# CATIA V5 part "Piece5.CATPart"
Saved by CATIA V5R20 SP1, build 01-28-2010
Part number: Piece5
Bounding box of the stored display mesh (mm): x -22.654 to 20.303, y 48.687 to 194.568, z -19.994 to 19.994
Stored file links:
  C:\Users\RENARD Simon\Documents\Cours IFMA\2ème année\IAO\Piece5.CATPart
  C:\Users\RENARD Simon\Documents\Cours IFMA\2ème année\IAO\Trainattero.CATProduct
  C:\Users\RENARD Simon\Documents\Cours IFMA\2ème année\IAO\Sqpiece5.CATPart
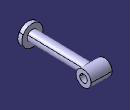
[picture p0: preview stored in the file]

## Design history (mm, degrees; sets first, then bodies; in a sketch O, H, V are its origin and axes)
Set1
  Plane1: linked copy from another document
  Line1: linked copy from another document
  Line2: linked copy from another document
  Plane2: linked copy from another document
Body1 (main body)
  Sketch1 on Plane1, origin (0, 0, 0), H (1, 0, 0), V (0, 1, 0)
    line L1 (-2.6637, 49.0966) -> (17.3321, 48.687)
    line L2 (17.3321, 48.687) -> (17.4959, 56.6854)
    line L3 (17.4959, 56.6854) -> (7.498, 56.8901)
    line L4 (7.498, 56.8901) -> (9.9979, 178.9573)
    line L5 (9.9979, 178.9573) -> (0, 179.162)
    line L6 (0, 179.162) -> (-2.6637, 49.0966)
    reference projected line E1 (-19.9958, 179.5716) -> (19.9958, 178.7525) from Line2
    reference projected line E2 (0, 179.162) -> (-2.6618, 49.1893) from Line1
    length L1 = 20
    length L2 = 8
    distance L4 L6 = 10
    coincidence: E1 L5, L6 E2
    parallelism: L3 L1
    perpendicularity: L4 L3, L1 L2
  Shaft1: profile Sketch1, axis Sketch1.L6, angle 360
  Sketch2 on Plane2, origin (16.3281, -0.3344, 0), H (0.0205, 0.9998, 0), V (0, 0, 1)
    circle A1 centre (179.1245, 0) radius 15
    point P1 (179.1245, 0)
    reference projected point E1 (179.1245, 0) from Line2
    radius A1 = 15
    coincidence: P1 E1
  Pad1: profile Sketch2, direction (-0.9998, 0.0205, 0), length 40
  Sketch3 on end face of Pad1, origin (-23.6635, 0.4846, 0), H (-0.0205, -0.9998, 0), V (0, 0, 1)
    circle A1 centre (-179.1245, 0) radius 7.5
    point P1 (-179.1245, 0)
    reference projected point E1 (-179.1245, 0) from Line2
    radius A1 = 7.5
    coincidence: P1 H, P1 E1
  Pocket1: profile Sketch3, direction (0.9998, -0.0205, 0), length 40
